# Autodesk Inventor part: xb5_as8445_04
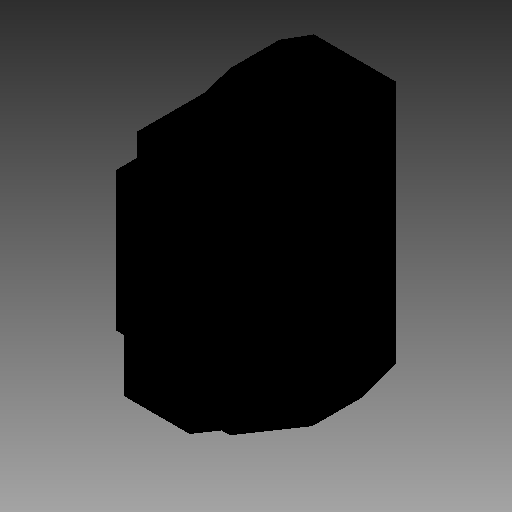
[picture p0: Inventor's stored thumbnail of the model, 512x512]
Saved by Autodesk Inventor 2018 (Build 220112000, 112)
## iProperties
Company: TraceParts S.A.
Created: 2018-04
Part Number: xb5_as8445_04
Checked By: TraceParts S.A.
Material: Generic
Catalog Web Link: www.traceparts.com
Document SubType Name: Modeling
Designer: TraceParts
Density: 1 g/cm^3
Appearance: Default
Author: TraceParts
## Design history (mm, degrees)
feature "xb5_as8445_04.ipt"
body "Solid1"
